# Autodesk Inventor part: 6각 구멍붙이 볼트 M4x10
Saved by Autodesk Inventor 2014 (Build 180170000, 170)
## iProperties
Created: 2026-08
Part Number: 6각 구멍붙이 볼트 M4x10
Material: 강철, 연강
Document SubType Name: Modeling
Designer: dg
Density: 7.86 g/cm^3
Appearance: 강철
Mass: 2.0371 g
Surface Area: 3.0572 cm^2
Volume: 0.259174 cm^3
Author: jhkim
Description: 6각머리 태핑 나사
Creation Date: 2026-07-31
Sending System: Autodesk Inventor 2027
Preprocessor: ST-DEVELOPER v20.1
Author: dg
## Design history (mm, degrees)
node "6각 구멍붙이 볼트 M4x101"
body "Solid1"
node "기준1"
